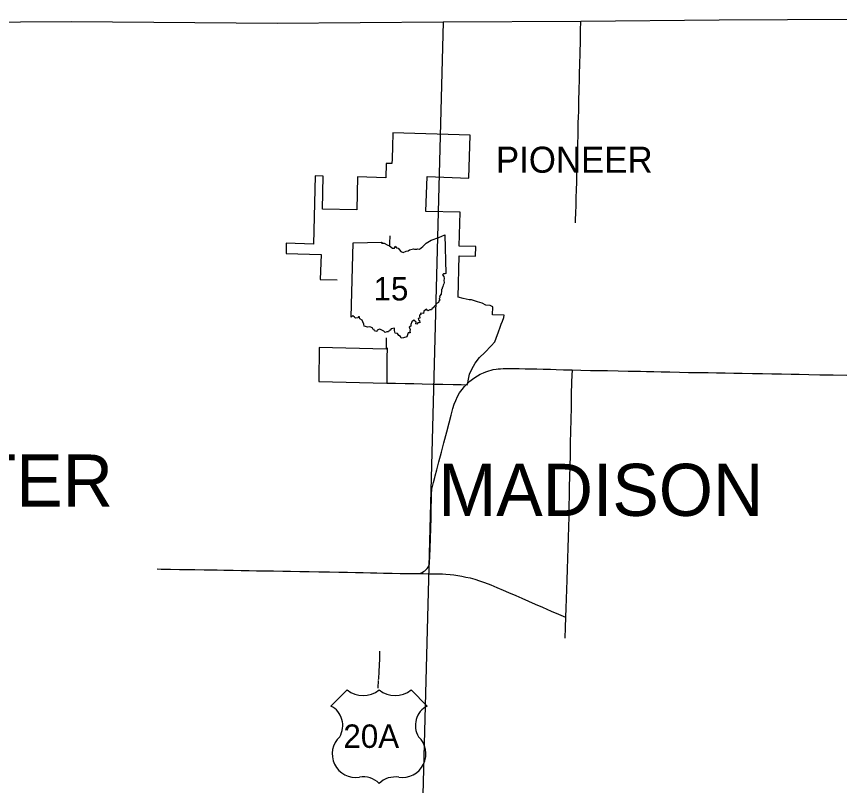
# Model space of a CAD drawing. Extents: x -232 to 448, y 619 to 1059.
# Drawn here: x -131.55 to -99.12, y 923.91 to 954.21 of the extents above; entities that cross this region are included whole.
import ezdxf

# ---------------------------------------------------------------- set-up
doc = ezdxf.new("R2010")
doc.units = 0
doc.layers.add('Default', color=7, linetype='Continuous')

msp = doc.modelspace()

# ---------------------------------------------------------------- linework, layer by layer
at = {"layer": 'Default'}
for p, q in [((-113.675, 949.525), (-116.728, 949.618)), ((-113.726, 947.833), (-113.675, 949.525)), ((-116.979, 948.419), (-116.997, 947.851)), ((-116.757, 948.413), (-116.979, 948.419)), ((-119.78, 947.928), (-119.854, 945.23)), ((-119.462, 947.919), (-119.78, 947.928)), ((-116.997, 947.851), (-118.119, 947.882)), ((-115.375, 947.895), (-113.726, 947.833)), ((-119.854, 945.23), (-120.92, 945.27)), ((-118.37, 942.365), (-118.288, 945.294)), ((-118.37, 942.365), (-118.288, 945.294)), ((-113.454, 945.148), (-114.114, 945.157)), ((-113.461, 944.757), (-113.454, 945.148)), ((-114.108, 944.771), (-113.461, 944.757)), ((-112.332, 942.442), (-112.796, 942.456)), ((-116.979, 941.546), (-116.989, 941.102)), ((-119.619, 941.17), (-119.637, 939.821)), ((-116.989, 941.102), (-119.619, 941.17)), ((-118.525, 927.676), (-119.159, 927.042)), ((-118.525, 927.676), (-119.159, 927.042)), ((-115.37, 927.042), (-116.004, 927.676)), ((-115.37, 927.042), (-116.004, 927.676))]:
    msp.add_line(p, q, dxfattribs=at)
for points in [[(-147.422, 953.89), (-129.376, 954.001), (-121.284, 953.944), (-114.736, 953.989)], [(-114.736, 953.989), (-109.321, 954.026), (-103.866, 954.073), (-98.476, 954.095), (-93.096, 954.205), (-87.688, 954.093)], [(-109.328, 954.026), (-109.339, 953.656), (-109.349, 953.236), (-109.358, 952.774), (-109.372, 952.303), (-109.382, 951.973)], [(-114.736, 953.989), (-115.571, 922.539)], [(-109.382, 951.973), (-109.387, 951.779), (-109.4, 951.275), (-109.408, 950.917), (-109.413, 950.528), (-109.425, 950.187)], [(-109.427, 950.133), (-109.428, 950.111), (-109.438, 949.611), (-109.451, 949.105), (-109.455, 948.943)], [(-109.425, 950.187), (-109.427, 950.133)], [(-116.728, 949.618), (-116.729, 949.594), (-116.739, 949.094), (-116.752, 948.589), (-116.757, 948.413)], [(-109.455, 948.943), (-109.466, 948.581), (-109.469, 948.456)], [(-109.469, 948.456), (-109.48, 948.082), (-109.481, 948.076)], [(-119.5, 946.609), (-119.462, 947.919)], [(-118.119, 947.882), (-118.143, 946.59)], [(-114.114, 945.157), (-114.07, 946.498), (-115.422, 946.525), (-115.375, 947.895)], [(-109.481, 948.076), (-109.493, 947.66), (-109.499, 947.387), (-109.508, 947.049), (-109.516, 946.72), (-109.522, 946.511), (-109.534, 946.149), (-109.537, 946.079)], [(-118.143, 946.59), (-119.5, 946.609)], [(-118.288, 945.294), (-117.151, 945.313), (-117.169, 945.278), (-117.062, 945.27), (-116.948, 945.208), (-116.852, 945.168), (-116.734, 945.075), (-116.663, 945.076), (-116.634, 945.152), (-116.58, 945.093), (-116.516, 945.083), (-116.405, 944.943), (-116.313, 944.912), (-116.204, 944.96), (-116.122, 944.968), (-116.062, 945.016), (-115.906, 945.056), (-115.863, 945.032), (-115.78, 945.037), (-115.739, 945.055), (-115.666, 945.039), (-115.54, 945.145), (-115.409, 945.271), (-115.209, 945.39), (-114.909, 945.502), (-114.672, 945.602), (-114.637, 944.082)], [(-118.288, 945.294), (-117.151, 945.313), (-117.169, 945.278), (-117.062, 945.27), (-116.948, 945.208), (-116.852, 945.168), (-116.734, 945.075), (-116.663, 945.076), (-116.634, 945.152), (-116.58, 945.093), (-116.516, 945.083), (-116.405, 944.943), (-116.313, 944.912), (-116.204, 944.96), (-116.122, 944.968), (-116.062, 945.016), (-115.906, 945.056), (-115.863, 945.032), (-115.78, 945.037), (-115.739, 945.055), (-115.666, 945.039), (-115.54, 945.145), (-115.409, 945.271), (-115.209, 945.39), (-114.909, 945.502), (-114.672, 945.602), (-114.637, 944.082)], [(-116.839, 945.562), (-116.85, 945.275), (-116.854, 945.154)], [(-120.92, 945.27), (-120.93, 944.871), (-119.543, 944.834)], [(-119.543, 944.834), (-119.58, 943.848), (-118.911, 943.834)], [(-114.143, 943.147), (-114.108, 944.771)], [(-114.637, 944.082), (-114.672, 944.061), (-114.727, 944.071), (-114.764, 944.028), (-114.718, 943.957), (-114.697, 943.882), (-114.716, 943.799), (-114.697, 943.731), (-114.71, 943.674), (-114.744, 943.617), (-114.756, 943.563), (-114.785, 943.505), (-114.783, 943.473), (-114.81, 943.448), (-114.805, 943.353), (-114.819, 943.3), (-114.814, 943.255), (-114.859, 943.243), (-114.849, 943.205), (-114.878, 943.176), (-114.872, 943.126), (-114.904, 943.095), (-114.873, 943.031), (-114.898, 943.011), (-114.919, 942.933), (-114.977, 942.917), (-115.092, 942.776), (-115.133, 942.722), (-115.179, 942.709), (-115.204, 942.653), (-115.26, 942.653), (-115.346, 942.615), (-115.401, 942.681), (-115.498, 942.602), (-115.509, 942.51), (-115.631, 942.513), (-115.626, 942.467), (-115.654, 942.454), (-115.678, 942.407), (-115.664, 942.325), (-115.721, 942.304), (-115.714, 942.257), (-115.678, 942.227), (-115.661, 942.136), (-115.722, 942.155), (-115.772, 942.078), (-115.823, 942.096), (-115.806, 942.161), (-115.893, 942.239), (-115.975, 942.177), (-116.018, 942.076), (-116.018, 942.009), (-116.079, 941.968), (-116.04, 941.873), (-116.047, 941.807), (-116.046, 941.745), (-116.122, 941.747), (-116.168, 941.579)], [(-114.637, 944.082), (-114.672, 944.061), (-114.727, 944.071), (-114.764, 944.028), (-114.718, 943.957), (-114.697, 943.882), (-114.716, 943.799), (-114.697, 943.731), (-114.71, 943.674), (-114.744, 943.617), (-114.756, 943.563), (-114.785, 943.505), (-114.783, 943.473), (-114.81, 943.448), (-114.805, 943.353), (-114.819, 943.3), (-114.814, 943.255), (-114.859, 943.243), (-114.849, 943.205), (-114.878, 943.176), (-114.872, 943.126), (-114.904, 943.095), (-114.873, 943.031), (-114.898, 943.011), (-114.919, 942.933), (-114.977, 942.917), (-115.092, 942.776), (-115.133, 942.722), (-115.179, 942.709), (-115.204, 942.653), (-115.26, 942.653), (-115.346, 942.615), (-115.401, 942.681), (-115.498, 942.602), (-115.509, 942.51), (-115.631, 942.513), (-115.626, 942.467), (-115.654, 942.454), (-115.678, 942.407), (-115.664, 942.325), (-115.721, 942.304), (-115.714, 942.257), (-115.678, 942.227), (-115.661, 942.136), (-115.722, 942.155), (-115.772, 942.078), (-115.823, 942.096), (-115.806, 942.161), (-115.893, 942.239), (-115.975, 942.177), (-116.018, 942.076), (-116.018, 942.009), (-116.079, 941.968), (-116.04, 941.873), (-116.047, 941.807), (-116.046, 941.745), (-116.122, 941.747), (-116.168, 941.579)], [(-112.787, 942.77), (-112.894, 942.824), (-113.055, 942.838), (-113.209, 942.916), (-113.381, 942.963), (-113.62, 943.046), (-113.719, 943.038), (-113.952, 943.093), (-114.143, 943.147)], [(-112.796, 942.456), (-112.787, 942.77)], [(-116.168, 941.579), (-116.301, 941.547), (-116.393, 941.528), (-116.426, 941.604), (-116.491, 941.644), (-116.534, 941.721), (-116.629, 941.732), (-116.651, 941.837), (-116.662, 941.923), (-116.791, 941.902), (-116.827, 941.849), (-116.872, 941.835), (-116.899, 941.783), (-116.961, 941.778), (-117.028, 941.753), (-117.072, 941.805), (-117.182, 941.857), (-117.232, 941.884), (-117.335, 941.842), (-117.357, 941.793), (-117.439, 941.815), (-117.458, 941.87), (-117.508, 941.886), (-117.519, 941.944), (-117.625, 941.976), (-117.707, 941.963), (-117.85, 942.01), (-117.859, 942.087), (-117.908, 942.18), (-117.933, 942.245), (-118.024, 942.295), (-118.042, 942.372), (-118.071, 942.37), (-118.098, 942.339), (-118.199, 942.324), (-118.239, 942.356), (-118.295, 942.41), (-118.37, 942.365)], [(-116.168, 941.579), (-116.301, 941.547), (-116.393, 941.528), (-116.426, 941.604), (-116.491, 941.644), (-116.534, 941.721), (-116.629, 941.732), (-116.651, 941.837), (-116.662, 941.923), (-116.791, 941.902), (-116.827, 941.849), (-116.872, 941.835), (-116.899, 941.783), (-116.961, 941.778), (-117.028, 941.753), (-117.072, 941.805), (-117.182, 941.857), (-117.232, 941.884), (-117.335, 941.842), (-117.357, 941.793), (-117.439, 941.815), (-117.458, 941.87), (-117.508, 941.886), (-117.519, 941.944), (-117.625, 941.976), (-117.707, 941.963), (-117.85, 942.01), (-117.859, 942.087), (-117.908, 942.18), (-117.933, 942.245), (-118.024, 942.295), (-118.042, 942.372), (-118.071, 942.37), (-118.098, 942.339), (-118.199, 942.324), (-118.239, 942.356), (-118.295, 942.41), (-118.37, 942.365)], [(-113.789, 939.697), (-113.774, 939.774), (-113.742, 939.911), (-113.703, 940.108), (-113.655, 940.237), (-113.548, 940.43), (-113.484, 940.548), (-113.308, 940.767), (-113.098, 940.97), (-112.843, 941.234), (-112.706, 941.392), (-112.65, 941.537), (-112.558, 941.782), (-112.496, 941.964), (-112.452, 942.078), (-112.399, 942.202), (-112.346, 942.351), (-112.332, 942.442)], [(-116.948, 941.15), (-116.953, 940.743), (-116.954, 940.152), (-116.963, 939.765)], [(-115.058, 936.106), (-114.993, 936.35), (-114.905, 936.667), (-114.806, 937.047), (-114.711, 937.408), (-114.599, 937.843), (-114.506, 938.2), (-114.43, 938.498), (-114.358, 938.766), (-114.304, 938.933), (-114.246, 939.077), (-114.176, 939.232), (-114.094, 939.373), (-113.993, 939.51), (-113.899, 939.629), (-113.795, 939.733), (-113.683, 939.836), (-113.582, 939.92), (-113.491, 939.983), (-113.391, 940.048), (-113.276, 940.11), (-113.156, 940.168), (-113.056, 940.208), (-112.94, 940.248), (-112.853, 940.272), (-112.764, 940.292), (-112.658, 940.312), (-112.569, 940.328), (-112.483, 940.331), (-112.373, 940.337)], [(-112.373, 940.337), (-112.357, 940.338), (-112.153, 940.334), (-112.046, 940.334)], [(-112.046, 940.334), (-111.956, 940.334), (-111.742, 940.332), (-111.515, 940.327), (-111.297, 940.323), (-111.054, 940.318), (-110.797, 940.312), (-110.515, 940.306), (-110.293, 940.297), (-109.999, 940.288), (-109.662, 940.282)], [(-109.662, 940.282), (-109.679, 939.824), (-109.693, 939.291), (-109.703, 938.808), (-109.713, 938.317), (-109.721, 937.872), (-109.733, 937.393), (-109.74, 936.941), (-109.75, 936.48), (-109.762, 936.067), (-109.773, 935.687), (-109.782, 935.306), (-109.786, 934.944), (-109.793, 934.494), (-109.807, 934.095), (-109.821, 933.68), (-109.832, 933.279), (-109.842, 932.859), (-109.857, 932.428), (-109.874, 931.996), (-109.882, 931.63), (-109.899, 931.264), (-109.908, 930.896), (-109.914, 930.54)], [(-109.662, 940.282), (-109.322, 940.272), (-108.931, 940.265), (-108.592, 940.259), (-108.261, 940.253), (-107.847, 940.243), (-107.454, 940.239), (-107.049, 940.229), (-106.968, 940.227)], [(-106.968, 940.227), (-106.726, 940.219), (-106.485, 940.214)], [(-106.485, 940.214), (-106.442, 940.213), (-106.15, 940.21), (-105.81, 940.202), (-105.426, 940.195), (-105.068, 940.186), (-104.687, 940.181), (-104.294, 940.174), (-103.969, 940.168), (-103.636, 940.162), (-103.294, 940.156), (-102.965, 940.153), (-102.557, 940.142), (-102.154, 940.137), (-101.786, 940.13), (-101.411, 940.121), (-101.033, 940.115), (-100.712, 940.11), (-100.333, 940.103), (-99.897, 940.094), (-99.376, 940.083), (-98.839, 940.079)], [(-119.637, 939.821), (-116.963, 939.765)], [(-116.963, 939.765), (-116.624, 939.755), (-116.233, 939.748), (-115.893, 939.742), (-115.562, 939.736), (-115.149, 939.726), (-114.756, 939.722), (-114.35, 939.712), (-114.027, 939.703), (-113.789, 939.697)], [(-126.006, 932.442), (-125.854, 932.439), (-125.488, 932.435), (-125.132, 932.426), (-124.809, 932.421), (-124.519, 932.416), (-124.157, 932.409), (-123.885, 932.408), (-123.64, 932.402), (-123.379, 932.397), (-123.015, 932.392), (-122.696, 932.386), (-122.387, 932.381), (-122.095, 932.373), (-121.762, 932.367), (-121.426, 932.361), (-121.052, 932.354), (-120.76, 932.349), (-120.383, 932.344), (-120.023, 932.336), (-119.638, 932.33), (-119.212, 932.322), (-118.85, 932.317), (-118.511, 932.313), (-118.192, 932.306), (-117.894, 932.297), (-117.606, 932.29), (-117.352, 932.287), (-117.085, 932.279), (-116.744, 932.273), (-116.429, 932.268), (-116.139, 932.263), (-115.896, 932.26), (-115.712, 932.263), (-115.636, 932.281), (-115.569, 932.308), (-115.511, 932.337), (-115.464, 932.368), (-115.418, 932.41), (-115.367, 932.462), (-115.333, 932.513), (-115.3, 932.573), (-115.28, 932.63), (-115.273, 932.711), (-115.269, 932.928), (-115.253, 933.257), (-115.242, 933.631), (-115.228, 934.059), (-115.217, 934.435), (-115.211, 934.842), (-115.199, 935.188), (-115.196, 935.455), (-115.192, 935.519), (-115.181, 935.586), (-115.164, 935.689), (-115.125, 935.846), (-115.073, 936.048), (-115.058, 936.106)], [(-115.712, 932.263), (-115.525, 932.257), (-115.32, 932.249), (-115.118, 932.247), (-114.955, 932.246), (-114.766, 932.243), (-114.63, 932.235), (-114.468, 932.221), (-114.323, 932.203), (-114.157, 932.179), (-114.001, 932.156), (-113.845, 932.123), (-113.673, 932.087), (-113.496, 932.036), (-113.306, 931.979), (-113.112, 931.911), (-112.868, 931.816), (-112.622, 931.71), (-112.38, 931.612), (-112.164, 931.517), (-111.882, 931.393), (-111.642, 931.287), (-111.378, 931.177), (-111.118, 931.06), (-110.821, 930.934), (-110.481, 930.784), (-110.193, 930.66), (-109.914, 930.54)], [(-109.914, 930.54), (-109.93, 930.133), (-109.942, 929.715)], [(-117.244, 929.198), (-117.244, 929.187), (-117.25, 928.907), (-117.277, 928.402), (-117.294, 928.11), (-117.295, 928.077)], [(-117.297, 928.043), (-117.31, 927.759), (-117.31, 927.751)]]:
    msp.add_lwpolyline(points, dxfattribs=at)
for centre, radius, start, end in [((-117.895, 928.477), 1.019, 231.813, 308.187), ((-117.895, 928.477), 1.019, 231.813, 308.187), ((-116.634, 928.477), 1.019, 231.813, 308.187), ((-116.634, 928.477), 1.019, 231.813, 308.187), ((-119.556, 926.276), 0.862, 329.1175, 62.6108), ((-119.556, 926.276), 0.862, 329.1175, 62.6108), ((-114.973, 926.276), 0.862, 117.3892, 210.8825), ((-114.973, 926.276), 0.862, 117.3892, 210.8825), ((-118.181, 925.154), 0.93, 133.0046, 278.7282), ((-118.181, 925.154), 0.93, 133.0046, 278.7282), ((-116.348, 925.154), 0.93, 261.2718, 46.9954), ((-116.348, 925.154), 0.93, 261.2718, 46.9954), ((-117.869, 923.42), 0.832, 43.4177, 101.8742), ((-117.869, 923.42), 0.832, 43.4177, 101.8742), ((-116.643, 923.364), 0.883, 79.9613, 134.7468), ((-116.643, 923.364), 0.883, 79.9613, 134.7468)]:
    msp.add_arc(centre, radius, start, end, dxfattribs=at)

# ---------------------------------------------------------------- texts
for s, height, p in [('PIONEER', 1.026, (-112.662, 948.05)), ('15', 0.9234, (-117.484, 943.018)), ('BRIDGEWATER', 2.052, (-148.177, 934.898)), ('MADISON', 2.052, (-114.935, 934.531)), ('20A', 0.9234, (-118.671, 925.392))]:
    msp.add_text(s, height=height, dxfattribs=at).set_placement(p)

doc.saveas('drawing.dxf')
